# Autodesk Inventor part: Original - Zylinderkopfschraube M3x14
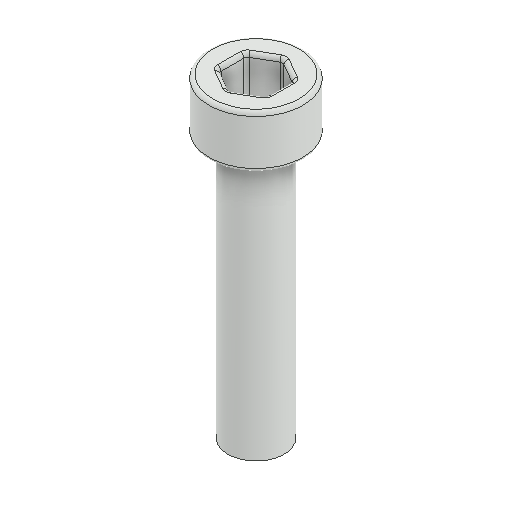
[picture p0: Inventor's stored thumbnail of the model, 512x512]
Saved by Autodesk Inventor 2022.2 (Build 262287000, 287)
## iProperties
Created: 2024-09
Part Number: Original - Zylinderkopfschraube M3x14
Material: Generico
Document SubType Name: Modeling
Designer: 18907419
Density: 1 g/cm^3
Appearance: Default
Author: 18907419
Revision Number: ANY
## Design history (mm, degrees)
feature "Verrundung3"
node "Solido1"
